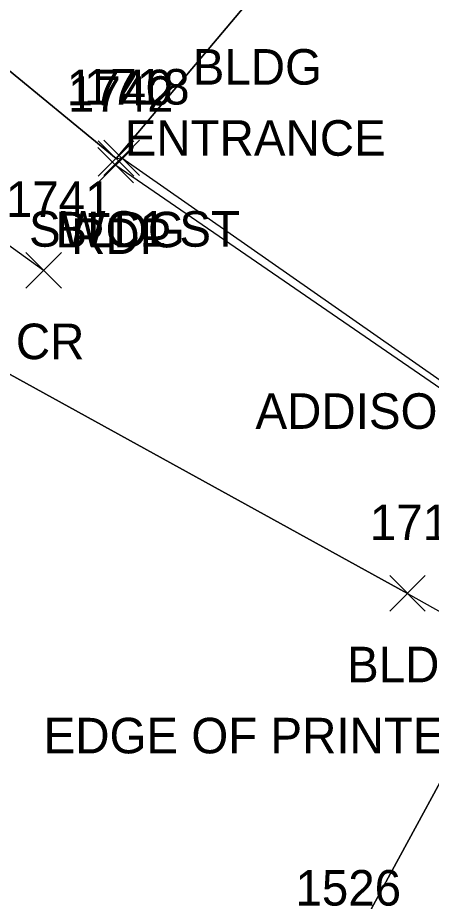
# Model space of a CAD drawing. Extents: x 1462668 to 1465147, y 550359 to 557351.
# Drawn here: x 1464618.84 to 1464642.16, y 552631.17 to 552680.52 of the extents above; entities that cross this region are included whole.
import ezdxf

# ---------------------------------------------------------------- set-up
doc = ezdxf.new("R2010")
doc.units = 0
for name, color, linetype in [('L_A', 7, 'Continuous'), ('L_C', 7, 'Continuous'), ('L_I', 7, 'Continuous'), ('L_TIC', 7, 'Continuous'), ('LBC', 7, 'Continuous'), ('Level 6', 7, 'Continuous'), ('P_A', 7, 'Continuous'), ('P_I', 7, 'Continuous'), ('P_TIC', 7, 'Continuous'), ('PET', 7, 'Continuous'), ('PRC', 7, 'Continuous'), ('R_A', 7, 'Continuous'), ('R_I', 7, 'Continuous'), ('R_TIC', 7, 'Continuous'), ('RSW', 7, 'Continuous'), ('S_C', 7, 'Continuous')]:
    doc.layers.add(name, color=color, linetype=linetype)

msp = doc.modelspace()

# ---------------------------------------------------------------- linework, layer by layer
at = {"layer": 'L_TIC'}
for points in [[(1464623.39, 552671.583), (1464625.39, 552673.583)], [(1464625.39, 552671.583), (1464623.39, 552673.583)], [(1464639.813, 552647.108), (1464641.813, 552649.108)], [(1464641.813, 552647.108), (1464639.813, 552649.108)]]:
    msp.add_lwpolyline(points, dxfattribs=at)
at = {"layer": 'LBC'}
for points in [[(1464565.634, 552720.492), (1464575.941, 552712.114), (1464605.178, 552688.357), (1464624.39, 552672.583), (1464632.118, 552681.74), (1464636.434, 552687.053)], [(1464640.813, 552648.108), (1464613.638, 552663.063), (1464591.148, 552675.073), (1464568.156, 552687.492)], [(1464624.39, 552672.583), (1464624.708, 552672.62)], [(1464640.813, 552648.108), (1464646.653, 552644.839)], [(1464637.245, 552627.541), (1464646.653, 552644.839)]]:
    msp.add_lwpolyline(points, dxfattribs=at)
at = {"layer": 'Level 6'}
msp.add_lwpolyline([(1464615.125, 552732.186), (1464637.452, 552714.014), (1464631.192, 552706.177), (1464643.539, 552696.027), (1464636.434, 552687.053), (1464632.118, 552681.74), (1464624.39, 552672.583), (1464605.178, 552688.357), (1464575.941, 552712.114), (1464565.634, 552720.492), (1464568.423, 552703.107), (1464566.906, 552691.193), (1464568.156, 552687.492), (1464591.148, 552675.073), (1464613.638, 552663.063), (1464640.813, 552648.108), (1464646.653, 552644.839), (1464637.245, 552627.541)], dxfattribs=at)
at = {"layer": 'P_TIC'}
for points in [[(1464623.373, 552671.212), (1464625.373, 552673.212)], [(1464625.373, 552671.212), (1464623.373, 552673.212)], [(1464619.312, 552665.291), (1464621.312, 552667.291)], [(1464621.312, 552665.291), (1464619.312, 552667.291)]]:
    msp.add_lwpolyline(points, dxfattribs=at)
at = {"layer": 'PET'}
msp.add_lwpolyline([(1464624.373, 552672.212), (1464646.04, 552657.334), (1464652.465, 552654.244), (1464655.954, 552652.528)], dxfattribs=at)
at = {"layer": 'PRC'}
msp.add_lwpolyline([(1464568.423, 552703.107), (1464598.394, 552682.108), (1464620.312, 552666.291)], dxfattribs=at)
at = {"layer": 'R_TIC'}
for points in [[(1464623.708, 552671.62), (1464625.708, 552673.62)], [(1464625.708, 552671.62), (1464623.708, 552673.62)]]:
    msp.add_lwpolyline(points, dxfattribs=at)
at = {"layer": 'RSW'}
msp.add_lwpolyline([(1464624.708, 552672.62), (1464646.202, 552657.628), (1464652.445, 552654.581), (1464655.968, 552652.732)], dxfattribs=at)

# ---------------------------------------------------------------- texts
at = {"layer": 'L_A'}
for p in [(1464628.709, 552676.74), (1464620.981, 552667.583), (1464637.403, 552643.108)]:
    msp.add_text('BLDG', height=2, dxfattribs=at).set_placement(p)
at = {"layer": 'L_C'}
for s, p in [('ENTRANCE', (1464624.874, 552672.74)), ('EDGE OF PRINTERS VALLEY', (1464620.309, 552639.108))]:
    msp.add_text(s, height=2, dxfattribs=at).set_placement(p)
at = {"layer": 'L_I'}
for s, p in [('1740', (1464621.611, 552675.583)), ('1712', (1464638.687, 552651.108)), ('1526', (1464634.497, 552630.541))]:
    msp.add_text(s, height=2, dxfattribs=at).set_placement(p)
at = {"layer": 'P_A'}
for s, p in [('RDP', (1464621.861, 552667.212)), ('CR', (1464618.745, 552661.291))]:
    msp.add_text(s, height=2, dxfattribs=at).set_placement(p)
at = {"layer": 'P_I'}
for s, p in [('1742', (1464621.68, 552675.212)), ('1741', (1464618.186, 552669.291))]:
    msp.add_text(s, height=2, dxfattribs=at).set_placement(p)
at = {"layer": 'R_A'}
msp.add_text('SWC1 ST', height=2, dxfattribs=at).set_placement((1464619.487, 552667.62))
at = {"layer": 'R_I'}
msp.add_text('1718', height=2, dxfattribs=at).set_placement((1464622.582, 552675.62))
at = {"layer": 'S_C'}
msp.add_text('ADDISON EAGLE & OTTER CREEK', height=2, dxfattribs=at).set_placement((1464632.244, 552657.37))

doc.saveas('drawing.dxf')
